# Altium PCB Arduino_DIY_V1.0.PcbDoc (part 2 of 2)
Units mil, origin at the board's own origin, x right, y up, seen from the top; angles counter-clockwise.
Board outline 4006.09 x 4935.69 mil, 2 copper layers (Top Layer, Bottom Layer), stack 46.063 mil thick; 121 components, 93 nets, 429 pads, 83 vias.
Unrouted connection lines stored in the file: 78.
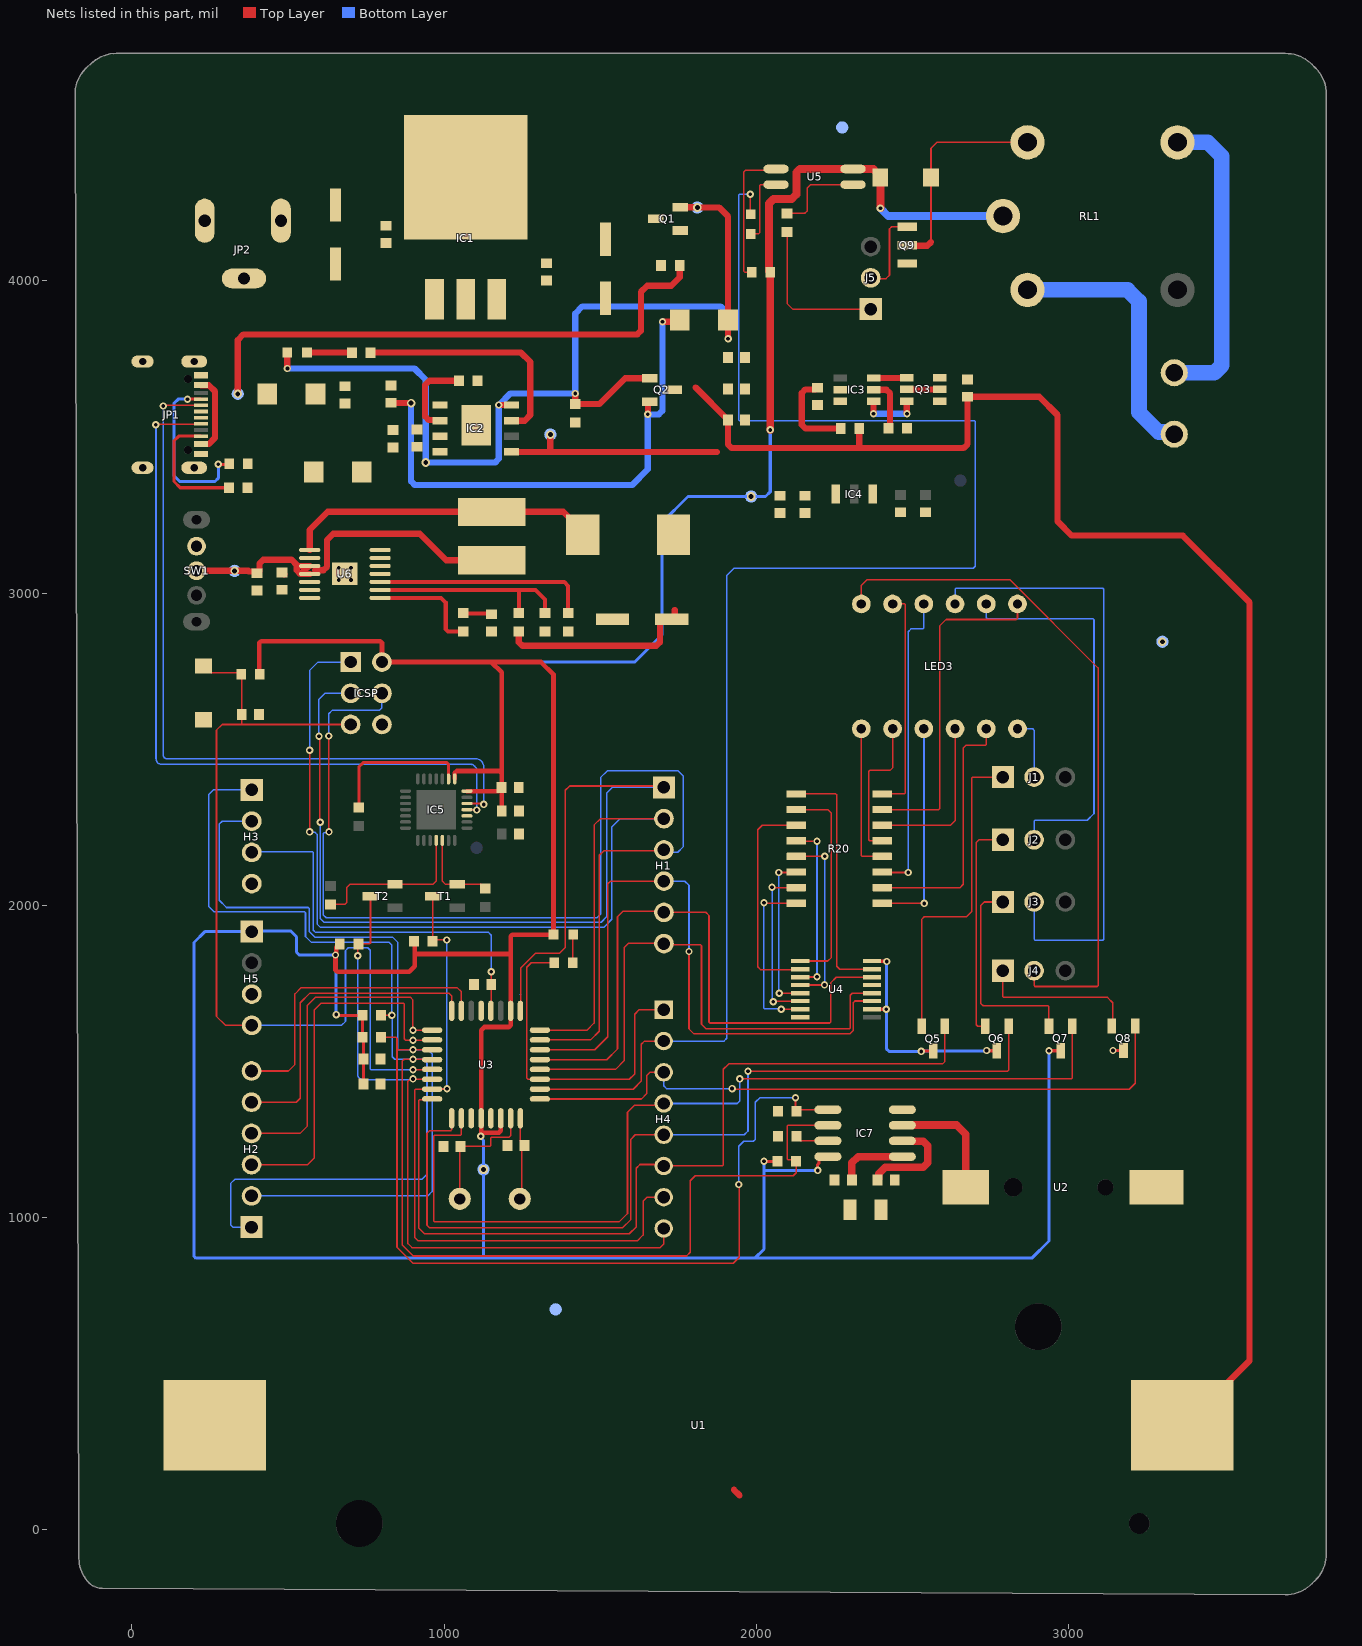
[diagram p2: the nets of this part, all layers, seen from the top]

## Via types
v1: diameter 23.62, hole 11.81, Top Layer to Bottom Layer, 65 vias
v2: diameter 27.56, hole 15.75, Top Layer to Bottom Layer, 11 vias
v3: diameter 24, hole 12, Top Layer to Bottom Layer, 4 vias
v4: diameter 157.48, hole 157.48, Top Layer to Bottom Layer, 3 vias

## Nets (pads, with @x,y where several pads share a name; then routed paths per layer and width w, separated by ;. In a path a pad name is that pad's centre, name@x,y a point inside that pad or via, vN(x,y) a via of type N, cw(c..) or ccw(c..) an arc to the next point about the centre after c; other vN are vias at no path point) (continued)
+5V: C15.1 C16.2 C17.2 C23.2 C24.2 C27.2 C28.2 D4.1 D5.1 H5.1 IC4.3 IC5.7 IC5.8 IC7.8 ICSP.6 LED2.1 Q5.3 Q6.3 Q7.3 Q8.3 R9.2 R11.2 R12.2 R15.2 R17.2 R18.2 R19.2 R21.2 R23.2 R24.2 RL1.5 TP6.1 TP8.1 U3.4 U3.6 U3.18 U4.10 U4.16 U5.4 | length 15890.7
  Top Layer w10: v1(654,1650) 656.61,1647.39 674.61,1647.39 675,1647 675.35,1647.35 R23.2@739,1647.35 R24.2@739,1577.35 ; C28.2@741.44,1427.35 C27.2@741.44,1507.35 R24.2@741.44,1574.91 ; v1(2024,1180) 2067.65,1180 R19.2@2068,1180.35 ; v1(2196,1151) 2195.46,1151.54 2195.46,1169.46 2200.06,1174.06 2200.06,1187.24 2208.17,1195.35 IC7.8@2229,1195.35 ; U4.10@2370.16,1667.56 2370.44,1667.28 2415.72,1667.28 v1(2416,1667) ; U4.16@2370.16,1821.56 2370.94,1820.78 2416.22,1820.78 v1(2417,1820) ; v1(2528,1532) 2530,1534 2538,1534 2538.44,1533.56 Q5.3@2566.16,1533.56 ; v1(2737,1535) 2737.81,1534.19 Q6.3@2770.16,1534.19 ; v1(2937,1534) 2944,1534 2944.19,1534.19 Q7.3@2974.16,1534.19 ; v1(3142,1535) 3142.18,1534.82 Q8.3@3175.56,1534.82
  Top Layer w15: R15.2@409.5,2740.35 408,2752.36 408,2840.14 413.86,2846 794.86,2846 800.72,2840.14 ICSP.6@800.72,2779 1151,2779 ; R12.2@665.69,1876 654.81,1865.12 654.81,1847.5 652,1844.69 v1(652,1841) 652,1792.86 657.86,1787 888,1787 906,1805 906,1844.26 ; R11.2@903.69,1885 906,1882.69 906,1844.26 ; IC5.8@1033.68,2404.73 1033.88,2404.93 1033.88,2423.83 1040.05,2430 1176,2430 1183.89,2422.11 ; IC5.7@1073,2365.4 1173.14,2365.4 1183.89,2376.15 C24.2@1183.89,2377.35 1183.89,2422.11 ; v1(1117,1260) 1118.25,1261.25 1118.25,1599.25 1129,1610 1206.88,1610 1212.74,1615.86 U3.18@1212.74,1662 1212.74,1848.03 ; 1124.11,1272 1175.39,1272 1181.24,1277.86 U3.6@1181.24,1318 ; C23.2@1184.44,2302.35 C24.2@1184.44,2376.8 ; 906,1844.26 1208.97,1844.26 1212.74,1848.03 ; 1151,2779 1310,2779 1350.22,2738.78 LED2.1@1350.22,1906.04 1218.6,1906.04 1212.74,1900.18 1212.74,1848.03 ; 1151,2779 1183.89,2746.11 1183.89,2422.11
  Top Layer w20: R9.2@1239.01,2877.04 1239.01,2842.72 1250.72,2831 1679.28,2831 1691,2842.72 1691,2908.09 1698.91,2916 C15.1@1728.48,2916 ; C15.1@1738.7,2916 1738.7,2945.3
  Top Layer w25: v1(2044.31,3522.31) R21.2@2044.31,4027 2040,4031.31 2040,4247.36 2054.64,4262 2113.36,4262 2128,4276.64 2128,4347 2139,4358 U5.4@2309.15,4358 2309.64,4357.51 2374.44,4357.51 2397,4334.95 D5.1@2397,4331 v1(2397,4232)
  Bottom Layer w10: v1(654,1650) 654,1839 v1(652,1841) 536,1841 527,1850 527,1899 508,1918 386.27,1918 H5.1@383.79,1915.52 233.52,1915.52 199,1881 199,875.86 204.86,870 1131,870 ; ICSP.6@800.72,2779 1610.59,2779 1697,2865.41 1697,3225 1781,3309 v2(1983,3309) 2029,3309 2044.31,3324.31 v1(2044.31,3522.31) ; v1(1117,1260) 1117,1256.31 1126,1247.31 1126,875 1131,870 ; v1(2024,1180) 2024,1151 ; v1(2196,1151) 2024,1151 ; v1(2417,1820) 2416.5,1819.5 2416.5,1667.5 v1(2416,1667) 2416,1541 2425,1532 v1(2528,1532) 2529.5,1533.5 2735.5,1533.5 v1(2737,1535) ; v1(2937,1534) 2937,925 2882,870 1995,870 ; 1131,870 1995,870 ; 1995,870 2024,899 2024,1151
  Bottom Layer w25: v1(2397,4232) 2422,4207 RL1.5@2789.47,4207
  other v2: 1126,1154
+5V_B: D1.2 D3.2 JP1.A9B4 JP1.B9A4 Q1.1 R3.2 TP1.1 | length 2034.9
  Top Layer w20: JP1.A9B4@221.83,3476.86 221.98,3477.02 245.95,3477.02 266,3497.07 266,3645.67 245.99,3665.68 221.98,3665.68 JP1.B9A4@221.83,3665.84 ; v2(339,3638) 339,3810 357,3828 1618.28,3828 1630,3839.72 1630,3964 1650,3984 1727,3984 1754.31,4011.31 R3.2@1754.31,4049
ADC0: H2.6 U3.23 | length 981.8
  Top Layer w5: H2.6@383,1469.35 501.35,1469.35 522,1490 522,1716 542.54,1736.54 1041.46,1736.54 1055.26,1722.74 U3.23@1055.26,1662
ADC1: H2.5 U3.24 | length 1016.7
  Top Layer w5: H2.5@383,1369.35 526.35,1369.35 539,1382 539,1688 570,1719 1015,1719 1023.76,1710.24 U3.24@1023.76,1662
ADC2: H2.4 U3.25 | length 1086.1
  Top Layer w5: H2.4@383,1269.35 538.35,1269.35 561,1292 561,1678 589,1706 891,1706 900,1697 v1(900,1600) ; v1@900.12,1600.12 961.38,1600.12 U3.25@961.5,1600.24
ADC3: H2.3 U3.26 | length 1181.6
  Top Layer w5: H2.3@383,1169.35 562.35,1169.35 584,1191 584,1665 606,1687 869.07,1687 872,1684.07 872,1572.37 876.37,1568 v1(900,1568) ; v1@904,1568 904.37,1568.37 961.13,1568.37 U3.26@961.5,1568.74
AREF: C29.2 H3.3 U3.20 | length 1267.8
  Top Layer w5: U3.20@1149.75,1662 1150.15,1662.4 1150.15,1745.6 1151,1746.44 v1(1151,1787)
  Bottom Layer w5: H3.3@383.79,2169.35 386.51,2172.07 578,2172.07 580.93,2169.14 580.93,1920.07 588,1913 1142,1913 1151,1904 v1(1151,1787)
DATA+: IC5.4 JP1.A6 JP1.B6 | length 2424
  Top Layer w5: v1(76,3539) 77.41,3540.41 220.41,3540.41 JP1.B6@221.82,3541.82 ; IC5.4@1073,2306.3 1073.59,2305.71 1104.06,2305.71 v1(1104.65,2305.12)
  Bottom Layer w5: v1(76,3539) 77.07,3537.93 77.07,2468.93 ccw(c94,2468.93) 94,2452 1082,2452 cw(c1082,2429.35) 1104.65,2429.35 v1(1104.65,2305.12)
DATA-: IC5.5 JP1.A7 JP1.B7 | length 2464.1
  Top Layer w5: v1(100,3599) 101.88,3600.88 JP1.B7@221.83,3600.88 ; IC5.5@1073,2326 1124,2326 v1(1127,2323)
  Bottom Layer w5: v1(100,3599) 100,2482 ccw(c113,2482) 113,2469 1101,2469 cw(c1101,2443) 1127,2443 v1(1127,2323)
DIG1: H4.6 Q5.1 U3.32 | length 2781.6
  Top Layer w5: U3.32@961.5,1379.76 959.07,1377.33 920.93,1377.33 918,1374.4 918,967 937,948 1593,948 1615,970 1615,1158 1627,1170 1698.24,1170 H4.6@1703,1165.24 1891.07,1165.24 1894,1168.17 1894,1475 1911,1492 2596,1492 2603.56,1499.56 Q5.1@2603.56,1612.3
DIG2: H4.5 Q6.1 U3.1 | length 2894.4
  Top Layer w5: U3.1@1023.76,1318 1023.76,1280.93 1020.83,1278 953,1278 945,1270 945,975 953,967 1571,967 1598,994 1598,1251 1612.24,1265.24 H4.5@1703,1265.24 ; v1(1973,1469) 2804.63,1469 2807.56,1471.93 Q6.1@2807.56,1612.93
  Bottom Layer w5: H4.5@1703,1265.24 1961.24,1265.24 1973,1277 v1(1973,1469)
DIG3: H4.4 Q7.1 U3.2 | length 3049.4
  Top Layer w5: U3.2@1055.26,1318 1055.26,1266.93 1052.33,1264 968.93,1264 966,1261.07 966,988.93 968.93,986 1560,986 1587,1013 1587,1337 1609,1359 1696.76,1359 H4.4@1703,1365.24 ; v1(1947,1444) 3008.63,1444 3011.56,1446.93 Q7.1@3011.56,1612.93
  Bottom Layer w5: H4.4@1703,1365.24 1938.24,1365.24 1947,1374 v1(1947,1444)
DIG4: H4.3 Q8.1 U3.9 | length 2215.1
  Top Layer w5: U3.9@1306.5,1379.76 1631.76,1379.76 1649,1397 1649,1455 1659.24,1465.24 H4.3@1703,1465.24 ; v1(1922,1413) 1924,1411 3194,1411 3212.96,1429.96 Q8.1@3212.96,1613.56
  Bottom Layer w5: H4.3@1703,1465.24 1703,1421.93 1711.93,1413 v1(1922,1413)
DS: H1.5 U3.13 U4.14 | length 1990.3
  Top Layer w5: U3.13@1306.5,1505.75 1520.75,1505.75 1555,1540 1555,1963 1573,1981 1700.14,1981 H1.5@1703.79,1977.35 1837.65,1977.35 1848,1967 1848,1625.93 1850.93,1623 2234,1623 2237.31,1626.31 2237.31,1751.31 2255.56,1769.56 U4.14@2370.16,1769.56
GND: C1.1 C2.1 C3.2 C4.2 C5.1 C6.1 C7.1 C9.1 C10.1 C11.1 C13.1 C14.1 C15.2 C16.1 C17.1 C18.1 C19.1 C20.1 C21.1 C22.1 C23.1 C24.1 C25.2 C26.2 C27.1 C28.1 C29.1 C30.2 C31.2 C32.2 H3.4 H5.3 IC1.2 IC1.4 IC2.1 IC2.3 IC2.9 IC4.1 IC5.3 IC7.4 ICSP.4 JP1.17 JP1.18 JP1.19 JP1.20 JP1.A12B1 JP1.B12A1 JP2.2 JP2.3 Q3.1 Q9.3 R1.1 R2.1 R3.1 R6.1 R7.1 R8.1 R26.1 R27.1 RESET.2 TP9.1 TP10.1 TP11.1 U2.2 U3.3 U3.5 U3.21 U4.8 U4.13 U6.6 U6.7 U6.11 U6.12 U6.13 U6.14 U6.15
  other v2: 3300,2844
  other v3: 662.31,3041.31 701.68,3041.31 662.31,3080.68 701.68,3080.68
MISO: H1.2 ICSP.1 U3.16 | length 3457
  Top Layer w5: v1@569,2234 v1(569,2496) ; U3.16@1306.5,1600.24 1457.24,1600.24 1480,1623 1480,2257 1500.35,2277.35 H1.2@1703.79,2277.35
  Bottom Layer w5: v1@569,2234 586,2234 592.99,2227.01 592.99,1940.01 604,1929 1511,1929 1537,1955 1537,2251 1563.35,2277.35 H1.2@1703.79,2277.35 ; v1(569,2496) 569,2752 596,2779 ICSP.1@700.72,2779
  other v1: 569,2235
MOSI: H1.3 ICSP.5 U3.15 | length 3778.9
  Top Layer w5: v1(630,2542) 630.5,2541.5 630.5,2235.5 v1(631,2235) ; U3.15@1306.5,1568.74 1468.74,1568.74 1497,1597 1497,2160 1512,2175 1701.44,2175 H1.3@1703.79,2177.35
  Bottom Layer w5: v1(630,2542) 630,2613 641,2624 792,2624 800,2632 800,2678.28 ICSP.5@800.72,2679 ; v1(631,2235) 628.77,2232.77 615.92,2232.77 612.99,2229.84 612.99,1969.01 622,1960 1489,1960 1501.93,1972.93 1501.93,1977.07 1501,1978 1501,2409 1523,2431 1749,2431 1765,2415 1765,2187 1747.86,2169.85 1714.99,2169.85 1713.14,2168 H1.3@1703.79,2177.35
NetC3_1: C3.1 C6.2 IC1.1 JP2.1
NetC4_1: C4.1 C5.2 IC1.3 Q1.3
NetC8_1: C8.1 C12.1 IC3.6 Q3.3 U1.2 | length 44.9
  Top Layer w20: U1.2@265.99,335 U1.2@285.48,335 ; 1928,128 1946,110
NetC8_2: C8.2 IC3.5 R5.1 | length 290.7
  Top Layer w20: C8.2@2195,3657.56 2189.39,3651.95 2156.72,3651.95 2145,3640.23 2145,3538.72 2156.72,3527 R5.1@2270,3527 ; IC3.5@2267.75,3652.81 IC3.5@2268.85,3651
NetC9_2: C9.2 C10.2 C11.2 C12.2 IC2.5 Q2.3 R5.2 TP3.1 U1.1 | length 6033.5
  Top Layer w20: IC2.5@1215.5,3452 1340,3452 ; v2(1340,3507.35) 1340,3452 ; 1805,3658.06 C11.2@1908.67,3554.39 ; 1873,3452 1340,3452 ; C11.2@1908.67,3553.96 1908.67,3475.72 1920.38,3464 2329.31,3464 ; R5.2@2329.31,3527 2329.31,3464 ; U1.1@3364.01,335 3372.32,335 3579,541.68 3579,2970 3365.05,3183.95 3010.05,3183.95 2964,3230 2964,3570 2905.55,3628.45 C12.2@2676,3628.45 2676,3477 2663,3464 2329.31,3464
NetC14_2: C14.2 L1.1 SW1.2 TP4.1 U6.3 U6.4 | length 1189.7
  Top Layer w20: SW1.2@207,3071.35 207.18,3071.18 328.82,3071.18 v2(329,3071) 372.78,3071 374.48,3069.3 395.25,3069.3 C14.2@401,3063.56 402.97,3063.56 408.72,3069.3 408.72,3094.65 420.43,3106.36 511.32,3106.36 527.9,3089.78 527.9,3072.72 539.61,3061 549.9,3061 U6.4@569.17,3061 ; 527.9,3086.59 U6.3@569.17,3086.59 ; 549.9,3070.9 U6.3@565.59,3086.59 ; 586.16,3073 613.28,3073 625,3084.72 625,3170 645,3190 922,3190 1007,3105 L1.1@1152,3105
NetC20_2: C20.2 U6.5 | length 10.1
  Top Layer w20: C20.2@481,3065.56 486.75,3059.81 C20.2@488.72,3059.81
NetC21_2: C21.2 R25.1 | length 91.8
  Top Layer w13: R25.1@1061,2936.35 1063.14,2934.2 1148.85,2934.2 C21.2@1151,2932.06
NetC31_1: C31.1 IC7.2 X2.2 | length 335.1
  Top Layer w24: C31.1@2388,1120.35 2391.75,1124.1 2391.75,1140.75 2412,1161 2533.94,1161 2548,1175.06 2548,1230.61 2533.94,1244.67 2467.68,1244.67 IC7.2@2467,1245.35
NetC32_1: C32.1 IC7.1 X2.1 | length 224.8
  Top Layer w24: C32.1@2305.55,1120.35 2305.5,1120.41 2305.5,1175.35 2325.5,1195.35 IC7.1@2467,1195.35
NetD4_2: D4.2 L1.2 U6.1 U6.2 | length 1000.6
  Top Layer w20: U6.1@569.17,3137.77 569.17,3202.18 627,3260 L1.2@1152,3260 1381.68,3260 1443.87,3197.81 D4.2@1443.87,3186
NetD5_2: D5.2 Q9.2 RL1.4 | length 699.2
  Top Layer w5: 2559,4123.72 D5.2@2559,4331 2559,4424 2578.22,4443.22 RL1.4@2868.21,4443.22
  Top Layer w20: Q9.2@2483,4114.06 2485.05,4112 2547.28,4112 2559,4123.72
NetH2_1: H2.1 H3.1 IC7.6 R19.1 R23.1 U3.28 | length 5405.3
  Top Layer w5: R23.1@798.31,1647.35 798.96,1648 v1(832.69,1648) ; v1(900,1507) 872,1507 866,1501 866,912 901,877 1776,877 1788,889 1788,1118 1804,1134 2118,1134 2127.31,1143.31 R19.1@2127.31,1180.35 2122.66,1185 2100.93,1185 2098,1187.93 2098,1292.42 2100.93,1295.35 IC7.6@2229,1295.35 ; v1@905,1507 905.63,1506.37 960.87,1506.37 U3.28@961.5,1505.75
  Bottom Layer w5: H2.1@383,969.35 323.65,969.35 316,977 316,1109 329,1122 928,1122 945,1139 945,1494.62 932.62,1507 v1(900,1507) 842,1507 834,1515 834,1646.69 v1(832.69,1648) 832.69,1872.31 824,1881 575,1881 556,1900 556,1976.07 553.07,1979 263,1979 246,1996 246,2355 260.35,2369.35 H3.1@383.79,2369.35
NetH2_2: H2.2 H3.2 IC7.5 R18.1 R24.1 U3.27 | length 5276.8
  Top Layer w5: R24.1@798.31,1577.35 846.07,1577.35 849,1574.42 849,1537.24 ; U3.27@961.5,1537.24 849,1537.24 ; v1(1943,1106) 1945,1104 1945,873 1926,854 900,854 849,905 849,1537.24 ; v1(2125,1384) 2125,1343.35 R18.1@2128,1340.35 2133,1345.35 IC7.5@2229,1345.35
  Bottom Layer w5: H2.2@383,1069.35 947.35,1069.35 961.19,1083.19 961.19,1524.81 948.76,1537.24 v1@907,1537.24 ; H3.2@383.79,2269.35 289.35,2269.35 280,2260 280,2016 303,1993 565.07,1993 568,1990.07 568,1916 587,1897 836,1897 852,1881 852,1540.17 854.93,1537.24 v1(900,1537.24) ; v1(1943,1106) 1943,1228 1959,1244 1990,1244 1996,1250 1996,1369 2011,1384 v1(2125,1384)
NetH6_1: H6.1 RL1.1 | length 869.5
  Bottom Layer w50: RL1.1@2868.21,3970.78 3188.22,3970.78 3225,3934 3225,3578.43 3287.85,3515.58 3330.99,3515.58 H6.1@3338,3508.57
NetH6_2: H6.2 RL1.3 | length 992.1
  Bottom Layer w50: H6.2@3338,3705.43 3466.44,3705.43 3490.66,3729.64 3490.66,4398.34 3445.8,4443.2 RL1.3@3348.53,4443.2
NetIC2_2: IC2.2 R6.2 | length 268.3
  Top Layer w20: IC2.2@986.5,3552 984.69,3553.81 950.72,3553.81 939,3565.53 939,3666.36 952.64,3680 R6.2@1047.69,3680
NetIC2_7: IC2.7 R4.2 | length 762.1
  Top Layer w20: R4.2@764.31,3770 1246,3770 1276,3740 1276,3570 1258,3552 IC2.7@1215.5,3552
NetIC3_1: IC3.1 Q3.6 | length 187.7
  Top Layer w20: v1(2375,3574) 2375.15,3574.15 IC3.1@2375.15,3613.6 ; Q3.6@2481,3614.6 2481.5,3614.1 2481.5,3574.5 v1(2482,3574)
  Bottom Layer w20: v1(2375,3574) v1(2482,3574)
NetIC3_2: IC3.2 R7.2 | length 171.2
  Top Layer w20: IC3.2@2375.15,3651 2416.28,3651 2428,3639.28 2428,3533.31 R7.2@2422.69,3528
NetIC3_3: IC3.3 Q3.4 | length 106.3
  Top Layer w20: IC3.3@2375.15,3688.4 2375.65,3688.9 2480.5,3688.9 Q3.4@2481,3689.4
NetIC5_9: IC5.9 R14.1 | length 471
  Top Layer w10: R14.1@727,2313.66 727,2443 741,2457 1008.12,2457 1013.98,2451.14 IC5.9@1013.98,2404.73
NetIC7_3: IC7.3 U2.1 | length 385.5
  Top Layer w25: IC7.3@2467,1295.35 2467.65,1296 2641,1296 2670.43,1266.57 U2.1@2670.43,1097
NetIC7_7: IC7.7 R17.1 | length 107.8
  Top Layer w5: R17.1@2128,1260.35 2128,1259.38 2141.38,1246 2228.35,1246 IC7.7@2229,1245.35
NetJ1_1: J1.1 Q5.2 | length 1042.7
  Top Layer w5: Q5.2@2528.76,1612.3 2528.76,1954.76 2537,1963 2673,1963 2689,1979 2689,2407.64 2691.93,2410.56 J1.1@2789.16,2410.56
NetJ1_2: J1.2 LED3.6 | length 205.8
  Bottom Layer w5: LED3.6@2836,2565 2885,2565 2889.93,2560.07 2889.93,2499.1 2889.16,2498.33 J1.2@2889.16,2410.56
NetJ2_1: J2.1 Q6.2 | length 703.1
  Top Layer w5: Q6.2@2732.76,1612.93 2708.38,1612.93 2704,1617.31 2704,2201 2712.78,2209.78 J2.1@2789.16,2209.78
NetJ2_2: J2.2 LED3.8 | length 1274.3
  Bottom Layer w5: LED3.8@2736,2965 2736,2920.93 2738.93,2918 3078.07,2918 3081,2915.07 3081,2294 3059,2272 2891.93,2272 2889,2269.07 2889,2209.94 J2.2@2889.16,2209.78
NetJ3_1: J3.1 Q7.2 | length 673.5
  Top Layer w5: J3.1@2789.16,2010.56 2729.56,2010.56 2719,2000 2719,1685 2726,1678 2933.83,1678 2936.76,1675.07 Q7.2@2936.76,1612.93
NetJ3_2: J3.2 LED3.9 | length 1991
  Bottom Layer w5: LED3.9@2636,2965 2636,3012.07 2638.93,3015 3109.07,3015 3112,3012.07 3112,1890.93 3109.07,1888 2893,1888 2889.16,1891.84 J3.2@2889.16,2010.56
NetJ4_1: J4.1 Q8.2 | length 518.4
  Top Layer w5: J4.1@2789.16,1790.56 2789.16,1707.77 2792.09,1704.84 3124.16,1704.84 3141,1688 3141,1616.4 Q8.2@3138.16,1613.56
NetJ4_2: J4.2 LED3.12 | length 2214.1
  Top Layer w5: LED3.12@2336,2965 2336,3024 2354.93,3042.93 2811.11,3042.93 3094,2760.03 3094,1742.91 3091.07,1739.98 2892.09,1739.98 2889.16,1742.91 J4.2@2889.16,1790.56
NetJ5_1: J5.1 R22.2 | length 505
  Top Layer w5: R22.2@2098,4156.69 2098,3927 2115.65,3909.35 J5.1@2366,3909.35
NetJ5_2: J5.2 Q9.1 | length 273.7
  Top Layer w5: J5.2@2366,4009.35 2368.42,4006.93 2415.21,4006.93 2426,4017.72 2426,4166 2433.11,4173.11 Q9.1@2483,4173.11
NetJP1_A5: JP1.A5 R1.2 | length 559.1
  Top Layer w10: v1(178,3621) 178.22,3620.78 221.61,3620.78 JP1.A5@221.82,3620.56 ; v1(277,3412) 309.34,3412 R1.2@311.69,3414.35
  Bottom Layer w10: v1(178,3621) 148,3621 135,3608 135,3375 153,3357 266,3357 277,3368 v1(277,3412)
NetJP1_B5: JP1.B5 R2.2 | length 408.1
  Top Layer w10: JP1.B5@221.82,3502.45 149.45,3502.45 135,3488 135,3357 155,3337 R2.2@311,3337
NetLED1_2: LED1.2 R4.1 | length 144.7
  Top Layer w10: R4.1@704.65,3770.35 R4.1@705,3770
  Top Layer w20: LED1.2@560.47,3770.35 R4.1@704.65,3770.35
NetLED2_2: LED2.2 R16.2 | length 90.6
  Top Layer w5: R16.2@1411.69,1816.04 1411.69,1904.57 LED2.2@1413.17,1906.05
NetLED3_1: LED3.1 R20.12 | length 473.5
  Top Layer w5: LED3.1@2336,2565 2336,2159.49 2338.93,2156.56 R20.12@2402.76,2156.56
NetLED3_2: LED3.2 R20.13 | length 469.1
  Top Layer w5: R20.13@2402.76,2206.56 2362.93,2206.56 2360,2209.49 2360,2429.07 2362.93,2432 2428,2432 2436,2440 LED3.2@2436,2565
NetLED3_3: LED3.3 R20.9 | length 693.9
  Top Layer w5: R20.9@2402.76,2006.56 2403.32,2006 v1(2537,2006)
  Bottom Layer w5: LED3.3@2536,2565 2536.5,2564.5 2536.5,2006.5 v1(2537,2006)
NetLED3_4: LED3.4 R20.14 | length 533.2
  Top Layer w5: R20.14@2402.76,2256.56 2621.56,2256.56 2636,2271 LED3.4@2636,2565
NetLED3_5: LED3.5 R20.10 | length 829.2
  Top Layer w5: R20.10@2402.76,2056.56 2651.56,2056.56 2662,2067 2662,2504 2670,2512 2733.07,2512 2736,2514.93 LED3.5@2736,2565
NetLED3_7: LED3.7 R20.15 | length 1075.6
  Top Layer w5: R20.15@2402.76,2306.56 2583.63,2306.56 2586.56,2309.49 2586.56,2894.56 2607.23,2915.23 2832.13,2915.23 2836,2919.1 LED3.7@2836,2965
NetLED3_10: LED3.10 R20.11 | length 986.9
  Top Layer w5: R20.11@2402.76,2106.56 2404.32,2105 v1(2486,2105)
  Bottom Layer w5: v1(2486,2105) 2486,2876 2495,2885 2533.07,2885 2536,2887.93 LED3.10@2536,2965
NetLED3_11: LED3.11 R20.16 | length 720.2
  Top Layer w5: R20.16@2402.76,2356.56 2474.07,2356.56 2477,2359.49 2477,2962.07 2474.07,2965 LED3.11@2436,2965
NetLED4_1: LED4.1 U5.2 | length 234.4
  Top Layer w5: LED4.1@1982,4149.88 1982.6,4150.47 2006.71,4150.47 2011,4154.77 2011,4305.07 2013.93,4308 U5.2@2062.85,4308
NetQ3_2: Q3.2 Q3.5 | length 106.3
  Top Layer w20: Q3.5@2481,3652 Q3.2@2587.31,3652
NetR9_1: R9.1 R26.2 U6.9 | length 657.5
  Top Layer w13: U6.9@794.83,3009.82 1238,3009.82 ; R9.1@1239.01,2936.35 1239.01,3008.81 1238,3009.82 ; R26.2@1323.01,2936.35 1323.01,2978.99 1292.18,3009.82 1238,3009.82
NetR20_1: R20.1 U4.15 | length 796.3
  Top Layer w5: R20.1@2127.56,2356.56 2254.07,2356.56 2257,2353.63 2257,1805.04 2266.47,1795.56 U4.15@2370.16,1795.56
NetR20_2: R20.2 U4.1 | length 683.8
  Top Layer w5: R20.2@2127.56,2306.56 2228.44,2306.56 2240,2295 2240,1833 2228.56,1821.56 U4.1@2140.16,1821.56
NetR20_3: R20.3 U4.2 | length 709.1
  Top Layer w5: R20.3@2127.56,2256.56 2018.56,2256.56 2004,2242 2004,1803 2013,1794 2138.6,1794 U4.2@2140.16,1795.56
NetR20_4: R20.4 U4.3 | length 543.7
  Top Layer w5: R20.4@2127.56,2206.56 2129.13,2205 2180,2205 ; U4.3@2140.16,1769.56 2140.88,1770.28 2193.28,1770.28 v1(2194,1771)
  Bottom Layer w5: v1(2194,1771) v1@2194,2207.13
  other v1: 2194,2205
NetR20_5: R20.5 U4.4 | length 582.4
  Top Layer w5: R20.5@2127.56,2156.56 2218.56,2156.56 v1(2219,2157) ; U4.4@2140.16,1744.56 2140.38,1744.78 2217.78,1744.78 v1(2218,1745)
  Bottom Layer w5: v1(2218,1745) 2217.57,1745.43 2217.57,1749.57 2219,1751 v1(2219,2157)
NetR20_6: R20.6 U4.5 | length 512.4
  Top Layer w5: v1(2071,2105) 2126,2105 R20.6@2127.56,2106.56 ; v1(2073,1718) 2073.28,1718.28 2139.88,1718.28 U4.5@2140.16,1718.56
  Bottom Layer w5: v1(2071,2105) 2071,1720 v1(2073,1718)
NetR20_7: R20.7 U4.6 | length 534
  Top Layer w5: v1(2050,2058) 2051,2057 2054,2057 2054.44,2056.56 R20.7@2127.56,2056.56 ; v1(2054,1691) 2055.28,1692.28 2138.88,1692.28 U4.6@2140.16,1693.56
  Bottom Layer w5: v1(2050,2058) 2050,1698 2054,1694 v1(2054,1691)
NetR20_8: R20.8 U4.7 | length 559.2
  Top Layer w5: v1(2024,2008) 2025,2007 2035,2007 2035.44,2006.56 R20.8@2127.56,2006.56 ; v1(2079,1667) 2079.28,1667.28 2139.88,1667.28 U4.7@2140.16,1667.56
  Bottom Layer w5: v1(2024,2008) 2024,1670.93 2026.93,1668 2077,1668 2078,1667 v1(2079,1667)
NetR21_1: R21.1 U5.1 | length 452.8
  Top Layer w5: R21.1@1985,4027 1963.05,4027 1958.75,4031.3 1958.75,4347.75 1965,4354 2058.85,4354 U5.1@2062.85,4358
NetR22_1: R22.1 U5.3 | length 292
  Top Layer w5: R22.1@2098,4216 2155,4216 2162,4223 2162,4296 2174,4308 U5.3@2309.15,4308
NetR25_2: R25.2 U6.8 | length 360
  Top Layer w13: U6.8@794.83,2984.23 989.77,2984.23 1005,2969 1005,2884.65 1012.62,2877.04 R25.2@1061,2877.04
NetR27_2: R27.2 U6.10 | length 694
  Top Layer w13: U6.10@794.83,3035.41 1384.59,3035.41 1397,3023 R27.2@1397,2936.35
PD7: H4.1 R16.1 U3.11 | length 1093.2
  Top Layer w5: R16.1@1352.38,1816.04 1279.04,1816.04 1264.31,1801.31 1264.31,1446.69 1268.24,1442.76 U3.11@1306.5,1442.76 1592.76,1442.76 1610,1460 1610,1651 1624.24,1665.24 H4.1@1703,1665.24
RELAY: H4.2 LED4.2 U3.10 | length 5071.3
  Top Layer w5: U3.10@1306.5,1411.26 1605.26,1411.26 1631,1437 1631,1555 1641.24,1565.24 H4.2@1703,1565.24 ; v1(1980,4277) 1980,4214.82 LED4.2@1982,4212.83
  Bottom Layer w5: H4.2@1703,1565.24 1896.24,1565.24 1905,1574 1905,3056 1928,3079 2694,3079 2701,3086 2701,3549.07 2698.07,3552 1945.93,3552 1943,3554.93 1943,4274.07 1945.93,4277 v1(1980,4277)
RESET: C30.1 H5.4 ICSP.3 R15.1 RESET.1 U3.29 | length 2968.4
  Top Layer w5: RESET.1@229.5,2766.38 253.77,2745 336.81,2745 R15.1@350.19,2740.35 351.74,2725.84 351.74,2625.57 C30.1@351.94,2610.35 351.41,2609.82 351.41,2579 ; H5.4@383.79,1615.52 299.48,1615.52 271,1644 271,2561 289,2579 351.41,2579 ; ICSP.3@700.72,2579 351.41,2579 ; v1@900,1473.63 960.87,1473.63 U3.29@961.5,1474.25
  Bottom Layer w5: H5.4@383.79,1615.52 671.52,1615.52 684,1628 684,1855 693,1864 755,1864 763,1856 763,1475.93 765.93,1473 v1(900,1473)
RX: H4.7 R11.1 T1.3 U3.31 | length 2167
  Top Layer w5: R11.1@963,1885 R11.1@963.63,1885.63 ; T1.3@963.63,2029.35 R11.1@963.63,1885.63 ; v1(1008,1889) 967,1889 R11.1@963.63,1885.63 ; v1(1009,1412) 1008.63,1411.63 961.87,1411.63 U3.31@961.5,1411.26 908.93,1411.26 906,1408.33 906,936 916,926 1619,926 1637,944 1637,1052.48 1649.76,1065.24 H4.7@1703,1065.24
  Bottom Layer w5: v1(1008,1889) 1008.5,1888.5 1008.5,1412.5 v1(1009,1412)
RX_TO_MCU: IC5.25 R10.1 T2.2 | length 528
  Top Layer w5: R10.1@636,2002.69 681.69,2002.69 688,2009 688,2057 697.75,2066.75 T2.2@842.37,2066.75 963.75,2066.75 974.58,2077.58 IC5.25@974.58,2207.88
SCK: H1.1 ICSP.2 U3.17 | length 3466.7
  Top Layer w5: v1(599,2541) 601,2539 601,2268 v1(603,2266) ; U3.17@1244.24,1662 1244.62,1662.38 1244.62,1798.62 1293,1847 1370,1847 1388,1865 1388,2368 1402,2382 1699.14,2382 H1.1@1703.79,2377.35
  Bottom Layer w5: v1(599,2541) 599,2660 618,2679 ICSP.2@700.72,2679 ; v1(603,2266) 603,2234 602.99,1958.01 615,1946 1503,1946 1520,1963 1520,2359 1538.35,2377.35 H1.1@1703.79,2377.35 ; 1243,1715 1245,1713
SH_CP: H1.4 U3.14 U4.11 | length 2142.4
  Top Layer w5: U3.14@1306.5,1537.24 1482.24,1537.24 1524,1579 1524,2069 1532.35,2077.35 H1.4@1703.79,2077.35 ; v1(1784,1852) 1784,1604 1800,1588 2299,1588 2310,1599 2310,1688 2315.56,1693.56 U4.11@2370.16,1693.56
  Bottom Layer w5: H1.4@1703.79,2077.35 1770.65,2077.35 1784,2064 v1(1784,1852)
ST_CP: H1.6 U3.12 U4.12 | length 1813.4
  Top Layer w5: U3.12@1306.5,1474.25 1548.25,1474.25 1577,1503 1577,1865 1591,1879 1702.14,1879 H1.6@1703.79,1877.35 1708.14,1873 1821.07,1873 1824,1870.07 1824,1619 1839,1604 2297.07,1604 2300,1606.93 2300,1712 2306.56,1718.56 U4.12@2370.16,1718.56
TX: H4.8 R12.1 T2.3 U3.30 | length 2256.7
  Top Layer w5: v1(723,1838) 723,1874 R12.1@725,1876 ; 741.31,1876.35 761.14,1876.35 764.07,1879.28 T2.3@764.07,2029.35 ; v1(900,1444) 896.44,1440.44 887.6,1440.44 884,1436.83 884,917 897,904 1691.76,904 1703,915.24 H4.8@1703,965.24 ; v1@907,1444 907.62,1443.38 960.88,1443.38 U3.30@961.5,1442.76
  Bottom Layer w5: v1(723,1838) 723,1458.44 ccw(c739.44,1458.44) 739.44,1442 v1@905,1442
TX_TO_MCU: IC5.26 R13.1 T1.2 | length 277.1
  Top Layer w5: IC5.26@994.28,2207.88 994.28,2076.72 1004.25,2066.75 T1.2@1042.37,2066.75 1118.6,2066.75 R13.1@1131,2054.35
VCC: C7.2 C13.2 D2.2 D3.1 IC2.4 IC2.8 LED1.1 Q1.2 Q2.1 R8.2 TP2.1 | length 3194.4
  Top Layer w20: LED1.1@497.52,3770.35 497.52,3719.48 v1(498,3719) ; v1(1175,3602) IC2.8@1215.5,3602 ; v1(1420,3639) R8.2@1420,3605 1497,3605 1579.8,3687.8 Q2.1@1658,3687.8 ; Q1.2@1755.74,4235.75 1756.35,4235.14 1810.21,4235.14 v2(1810.82,4234.53) 1880.47,4234.53 1909.16,4205.84 D2.2@1909.16,3874.05 v1(1909.16,3814.16)
  Bottom Layer w20: v1(498,3719) 905,3719 941,3683 v2(941,3418) 1163.28,3418 1175,3429.72 v1(1175,3602) 1212,3639 v1(1420,3639) 1420,3895 1442.84,3917.84 1885.17,3917.84 1909.16,3893.84 v1(1909.16,3814.16)
VIN: C1.2 C2.2 D1.1 D2.1 Q2.2 SW1.1 | length 1713.9
  Top Layer w20: C1.2@830,3609.45 830.72,3608.72 893.28,3608.72 v2(894,3608) ; v1(1652,3572) 1652.69,3572.69 1652.69,3609.22 1656.47,3613 Q2.2@1658,3613 ; v1(1699,3869) 1749.78,3869 D2.1@1754.84,3874.05
  Bottom Layer w20: v2(894,3608) 894,3357.72 905.72,3346 1602,3346 1652,3396 v1(1652,3572) 1687.28,3572 1699,3583.72 v1(1699,3869)
XTAL1: C25.1 U3.7 X1.2 | length 412.8
  Top Layer w5: X1.2@1049.94,1060 1049.94,1225.38 C25.1@1052.56,1228 1146.07,1228 1149,1230.93 1149,1254.07 1151.93,1257 1207.48,1257 1212.74,1262.26 U3.7@1212.74,1318
XTAL2: C26.1 U3.8 X1.1 | length 269.9
  Top Layer w5: X1.1@1242.06,1060 1248,1065.94 1248,1219.48 C26.1@1257.56,1229.03 ; U3.8@1244.24,1318 1244.24,1249.15 1244.31,1249.07 1244.31,1244.25 C26.1@1257.56,1231
  Top Layer w20: C26.1@1257.56,1229.03 C26.1@1257.56,1231
pads on no net: IC2.6 IC3.4 IC5.1 IC5.2 IC5.10 IC5.11 IC5.12 IC5.13 IC5.14 IC5.15 IC5.16 IC5.17 IC5.18 IC5.19 IC5.20 IC5.21 IC5.22 IC5.23 IC5.24 IC5.27 IC5.28 IC5.29 J1.3 J2.3 J3.3 J4.3 J5.3 JP1. JP1.A8 JP1.B8 RL1.2 SW1.3 SW1.4 U1. U2. U3.19 U3.22 U4.9
copper on no net:
  other v4: 3,-3.05 3.12,4559.07 3635,4560

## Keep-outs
Keep-Out Layer:
  lines w7.87: -133.61,4692.28 ccw(c-63.14,4595.96) -181.06,4614.33 -169.44,-91.6 ccw(c-57.87,-91.6) -136.76,-170.5 ; -130.96,4694.59 cw(c-49.9,4613.53) -49.9,4728.17 3608.61,4728.17 ; 138.25,4728 145,4728 ; 3608.61,4728 3694,4728 cw(c3694,4607.29) 3779.35,4692.65 3789.65,4682.35 cw(c3704.29,4597) 3825,4597 3825,-75.9 ccw(c3826.56,-75.9) 3825.46,-77 ; 3651.31,4728 3653,4728 ; 3825.03,-76.52 cw(c3704.32,-76.52) 3789.67,-161.88 3779.38,-172.17 cw(c3694.03,-86.81) 3694.03,-207.52 -95.74,-187.49 cw(c-95.74,-129.48) -136.76,-170.5 ; -136.76,-170.5 -136.76,-170.5

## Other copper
Top Layer:
  region net +5V: 1202,1822 1203,1813 1203,1628 1193,1619 1192,1619 1120,1619 1104,1603 1104,1243 1109,1243 1129,1243 1133,1243 1134,1591 1140,1597 1214,1597 1227,1610 1227,1818 1225,1820
  region net NetC8_1: 3152,3364 3728,3364 3787,3305 3787,3053 3694,3053 3692,3051 3687,3056 3687,3211 3634,3264 3152,3264
  region net +5V: 2028,4044 2060,4044 2060,3505 2034,3505 2028,3505
  region net +5V: 2055,1211 2037,1193 2037,1186 2062,1186 2063,1187
  region net +5V: 2052,1360 2087,1360 2087,1160 2052,1160
  region net +5V: 2087,1160 2009,1160 2008,1161 2008,1197 2087,1197
  region net +5V: 2224,1185 2224,1184 2205,1165 2200.06,1169.94 2200.06,1187.24
  region net +5V: 2185,1203 2193,1211 2273,1211 2273,1181 2189.19,1181
  region net +5V: 2185,1139 2210,1139 2210,1203 2185,1203
  region net NetC31_1: 2372,1139.77 2419,1139.77 2419,990 2372,990
  region net NetC32_1: 2278,1139.77 2323,1139.77 2323,990 2278,990
  region net +5V: 3125.4,1559.26 3190.4,1559.26 3190.4,1509.26 3125.4,1509.26
  region net +5V: 2924,1558.63 2989,1558.63 2989,1508.63 2924,1508.63
  region net +5V: 2720,1558.63 2785,1558.63 2785,1508.63 2720,1508.63
  region net +5V: 2516,1558 2581,1558 2581,1508 2516,1508
  region net +5V: 2340,1677 2430,1677 2430,1656 2340,1656
  region net +5V: 2340,1831 2430,1831 2430,1810 2340,1810
  region net +5V: 931.2,1803.2 946.8,1818.8 936.8,1828.8 924.8,1828.8
  region net +5V: 915,1870 915,1869 941,1843 931,1833 923.68,1833 897.69,1858.99
  region net +5V: 874,1842 874,1903 921,1903 921,1902 921,1842
  region net +3V3: 709,2158 682,2131 682,2129 722,2129 730,2137
  region net +3V3: 349,1847 349,1781 485,1781 512,1808 512,2076 530,2094 729,2094 744,2109 744,2271 706,2271 706,2140 479,2140 457,2118 457,2110 457,1862 445,1847
  region net +5V: 1140,2749 1172,2707.5 1198,2707.5 1236.5,2749
  region net +5V: 1259,2746 1302,2703 1363,2703 1407,2747 1409,2756
  region net +5V: 1227,2836 1196,2805 1196,2802 1245,2802 1246,2803
  region net +5V: 684.5,1826.5 724,1787 716,1779 665.86,1779 654.93,1789.93
  region net +5V: 1373,1878 1374,2798 1287,2798 1281,2804
  region net +5V: 1288,2742 1288,1945 1264,1921 1200,1921 1187,1908 1187,1860 1180,1853 882,1853 874,1845 874,1815 860,1801 685.46,1801 685.46,1893 639,1893 639,1782 653,1768 918,1768 933,1783 933,1815 1241,1815 1286,1860 1356,1860 1373,1878
  region net +5V: 1150,2444 1170,2464 1171,2464 1171,2435 1176,2430
  region net +5V: 1168,2403 1168,2762 1167.44,2762.56 1170.89,2766 1201,2766 1201,2401.26
  region net +5V: 1674,2896 1674,2854 1664,2844 1265,2844 1256,2853 1256,2893 1221,2893 1221,2816 1237,2816 765,2816 765,2743 765,2739 767,2739 1762,2739 1787,2764 1787,2896
  region net NetC8_1: 2719.55,3761 2325,3761 2324,3760 2324,3743.46
  region net NetC8_1: 3053,3412 3084.12,3443.12 3206.12,3338.12 3185,3317 3148,3317 3095,3370
  region net NetC8_1: 3556,102 3521,67 3195,67 3180,82 3180,129
  region net +3V3: 619,2075 619,2128 653,2128 653,2123 653,2075
  region net +3V3: 902,2006 902,2002 902,1977 816,1977 816,2006
  region net +3V3: 1088,2198 1088,2170 1184.44,2170 1184.44,2198
  region net +3V3: 1173,2028 1173,2026 1149,2002 1163,1988 1183,1988 1183,2009 1194,2020
  region net +3V3: 1017,1976 1017,2011 1167,2011 1167,2251 1203,2251 1203,1994 1185,1976
  region net +5V: 1146,2424 1147,2424 1179,2392 1183.89,2396.89 1183.89,2422.11 1173.89,2422.11 1160,2436
  region net +5V: 1042,2387 1042,2418 1045,2421 1168,2421 1168,2285 1169,2284 1201,2284 1201,2427 1184,2444 1034,2444 1025,2435 1025,2387
  region net +3V3: 2275,3136 2350,3136 2350,3355 2431,3355 2431,3291 2676,3291 2676,3388 2275,3388
  region net +5V: 1787,2896 1674,2896 1674,3301.84 1720.16,3348 2268,3348 2268,3285.56 1830.14,3285.56 1787,3242.42
  region net NetC14_2: 600,3061 625,3061 635.5,3071.5 635.5,3151 652,3169 659,3169 908,3169 974,3103 974,3060 1077,3060 1075,3150 1006,3150 950,3206 634,3206 615,3187 615,3102.75 610.82,3097 601,3097
  region net NetD4_2: 1237,3305 1472,3305 1501,3279 1501,3120 1381,3120 1381,3195 1357,3215 1237,3215
  region net NetD4_2: 534,3146 534,3263 575.7,3304.7 1045.26,3304.7 1045.26,3215.26 1045,3215 635,3215 607,3187 607,3144
  region net NetD4_2: 534,3146 534,3105 607,3105 607,3146
  region net NetC14_2: 503,3094 510,3087 515,3087 515,3093.46 519.61,3098.07
  region net NetC20_2: 563,3029 505,3029 488.72,3050 488.72,3059.81 497,3061 511.85,3042 562.58,3042 569.17,3035.41
  region net NetC14_2: 423,3116 316,3116 301,3101 301,3090
  region net NetC14_2: 175,3101 175,3039 424,3039 439,3053 439,3089 443.26,3092.73 508.95,3092.73 508.95,3076.05 534,3051 604,3051 604,3097 535,3097 415,3116 319,3101
  region net NetC9_2: 1312,3533 1370,3533 1370,3454 1312,3454
  region net NetC9_2: 1192,3467 1720,3467 1720,3402 1192,3402
  region net NetC9_2: 2720,3415 2816,3319 2848,3319 2848,3412 2850,3414
  region net NetC9_2: 2800,3462.53 2800,3166 2881,3085 3371,3085 3371,3142 3374,3145 3317,3202 2971,3202 2971,3445 2949,3467
  region net NetC9_2: 3441,541 3350,450 3350,443 3444,443 3495,494 3495,544
  region net NetC9_2: 3388.73,479 3428,479 3428,2989 3292,3125 2978,3125 2923,3180 2923,3510 2972,3510 2972,3278 3024,3226 3534,3226 3607,3153 3607,404 3512.56,309.56
  region net NetC8_1: 3207.45,174 3564,174 3649,259 3649,3259 3657,3267 3787,3267 3787,156 3762.5,131.5 3698,67 3229,67 3182,114
  region net NetC8_1: 102,480 3014,480 3014,221 3061,174 3212,174 3212,69 3210,67 836,67 835,68 837,70 837,164 102,164
  region net NetC8_1: 3089,3761 3122,3730.7 3122,3363 3220,3363 3220,3264 3064,3264 3021,3307 3021,3641
  region net NetC8_1: 2564,3679 2564,3673 2568,3669 2991,3669 2994,3669 3016,3645.64 3021,3641 3023,3643 3059,3669 3089,3761 2572,3761
  region net NetC8_1: 2549.45,3725.79 2564,3711.24 2564,3677.24 2608,3677.24 2609,3678.24 2608,3679.24 2608,3724.76
  region net NetC8_1: 2350,3760 2585,3760 2608,3737 2608,3722 2572,3722 2569,3722 2565,3722 2548,3722 2350,3722
  region net NetC8_1: 2290,3628 2301,3628 2305,3632 2305,3741 2324,3760 2350,3760 2350,3722 2336,3708.7 2336,3620 2314,3598 2288.79,3598
  region net NetC9_2: 2694,3645 2974,3645 2974,3267 2956,3270 2956,3447 2694,3447
  region net NetC9_2: 2657,3645 2695,3645 2695,3477 2659,3477 2657,3477
  region net NetC9_2: 2313,3544 2346,3544 2346,3481 2345,3480 2313,3480
  region net NetC9_2: 1919,3501 1943,3477 1943,3473 1917.67,3473 1914.52,3469.86
  region net NetC9_2: 1886,3525 1887,3524 1887,3402 2851,3402 2851,3488 2593,3488 1925,3488 1925,3525
  region net NetIC3_1: 2459,3627 2504,3627 2504,3558 2459,3558
  region net NetIC3_1: 2353,3626 2398,3626 2398,3559 2353,3559
  region net NetC8_1: 2177.28,3628 2290.5,3628 2290.5,3598 2212.72,3598 2212.72,3586.7 2177.28,3586.7
  region net NetC8_2: 2177.28,3673.3 2231,3673.3 2231,3662.81 2290.5,3662.81 2290.5,3639.19 2247.19,3639.19 2233,3639.19 2177.28,3639.19
  region net VCC: 1730,4260 1916,4260 1945,4231 1945,3799 1878,3799 1878,4200 1869,4209 1730,4209
  region net VIN: 1683,3910 1788,3910 1788,3839 1683,3839
  region net VIN: 1631,3629 1631,3555 1684,3555 1684,3629
  region net NetC9_2: 1711,3772 1711,3402 1925.19,3402 1925.19,3772
  region net VCC: 1573.64,3633.64 1608,3668 1572,3668
  region net VCC: 1403,3588.51 1403,3651 1517,3651 1531,3665 1531,3688 1545,3702 1686,3702 1686,3663 1576,3663 1576,3606 1558.51,3588.51
  region net VCC: 701,3352 1018,3352 1020,3352 1020,3466 933,3466 933,3486 701,3486
  region net +5V_B: 476,3466 526,3466 547,3445 547,3353 617,3353 628,3353 628,3520 590,3558 476,3558
  region net +5V_B: 383,3798 376,3798 362,3784 362,3654 300,3654 300,3818 342,3860 383,3860
  region net +5V_B: 1609,3874 1589,3854 1598,3845 1611,3845
  region net +5V_B: 1666,3859 1666,3869 1656,3869 1656,3859
  region net +5V_B: 1666,3860 1666,3830 1634,3798 382,3798 382,3848 382,3860
  region net +5V_B: 1731,4031 1705,4005 1640.75,4005 1606.49,3970.75 1606.49,3851 1649,3851 1666,3868 1666,3957 1735.96,3957 1780.96,4002 1780.96,4031
  region net +5V_B: 1731,4175 1781,4175 1781,4031 1740,4031 1738,4031 1736,4031 1731,4031
  region net VIN: 555,3672 621,3672 621,3642 638,3625 908,3625 908,3591 566,3591 555,3602
  region net +5V_B: 199,3677 276,3677 276,3654 199,3654
  region net +5V_B: 199,3488 276,3488 276,3466 199,3466
  region net +5V_B: 252.93,3677 476,3677 476,3466 252.93,3466
  region net NetC4_1: 1479,4003 1650,4162 1650,4217 1710,4217 1710,4118 1545.28,3958.45
  region net NetC4_1: 1130,4028 1130,3875 1549,3875 1549,4018 1549,4028
  region net NetC3_1: 439,4116 678.43,3876.57 1005,3876.57 1005,4013 977,4013 851,4139 610,4139 578,4171 578,4265 439,4265
  region net NetC3_1: 440,4265 509,4265 510,4264 510,4115 440,4115
Bottom Layer:
  region net +5V: 2379,4263 2848,4263 2848,4151 2379,4151
  region net +5V: 2023,3368 1992.5,3337.5 2005.69,3324.31 2044.31,3324.31
  region net +5V: 2020,3534 2069,3534 2069,3296 2034,3261 1998,3261 1998,3344 1997,3345 2020,3345
  region net +5V: 2038,1164 2213,1164 2213,1133 2037,1133
  region net +5V: 2002,898 2002,1199 2041,1199 2041,899 2042,898
  region net +5V: 1103,1131 1103,894 1145,894 1145,897 1146,903 1146,1133
  region net +5V: 295,1889 240,1834 224,1834 224,1890.52 216.26,1898.26
  region net +5V: 349,1952 188,1952 169,1933 169,1878 377.38,1878
  region net +5V: 254,1932 199,1932 169,1902 169,844 202,811 214,811 2946,811 3009,874 3009,1527.37 3011.56,1529.93 3003.49,1538 2883,1538 2883,927 2864,908 2826,908 307,908 254,961
  region net +5V: 2401,1837 2441,1837 2441,1576 2449,1568 3170,1568 3170,1519 3169.81,1518.81 2422.19,1518.81 2403,1538
  region net +5V: 600,1809 600,1804 638,1766 652,1780 652,1816.93
  region net +5V: 474,1899 474,1886 519,1841 529,1851 529,1884
  region net +5V: 348,1951 349,1952 531,1952 545,1938 545,1895 581,1859 664,1859 670,1853 670,1636 618,1636 618,1802 512,1802 499,1815 499,1878 348,1878
  region net VCC: 1439,3553 1439,3551 1432,3544 1280,3544 1280,3563 1278,3565
  region net VCC: 845.45,3708.55 931,3623 963.45,3623
  region net VCC: 1321,3564 1316,3564 1273,3521 1247,3547 1247,3567 1255,3567 1285,3597
  region net VCC: 1372,3777 1317,3722 1351,3722 1372,3701 1395,3724 1395,3745
  region net +5V: 1103,1273 1146,1273 1146,1130 1103,1130
  region net +3V3: 871,2003 871,2014 901,2014 915,2000 915,1999
  region net +3V3: 871,1987 883,1975 1090.95,1975 1119,2005 1119,2141 1079,2141 1079,2017 1067,2005 871,2005
  region net +3V3: 871,2008 871,2089 860,2100 624,2100 624,2126 889,2126 901,2114 901,2007
  region net +3V3: 1791,2781 1692,2682 1692,2678 1819,2678 1828,2669
  region net +3V3: 2594.96,3381 2683,3381 2683,3157 2659,3133 1875,3133 1863,3121 1863,2692 1821,2650 1416,2650 1381,2615 1381,2164 1355,2138 1079,2138 1079,2222 1249,2222 1291,2264 1290,2265 1290,2679 1346,2735 1780,2735 1780,3156 1836,3212 2573,3212 2597,3236
  region net +5V: 767,2814 768,2813 768,2745 1687,2745 1695,2745 1762,2808 1762,3194 1829,3261 2003,3261 2003,3345 1735,3345 1634,3244 1633,3244 1633,2871 1576,2814 774,2814
  region net VIN: 835,3538 912,3538 912,3368 917,3363 1593,3363 1631,3401 1631,3555 1714,3555 1714,3358 1636,3280 877.57,3280 835,3322.57
  region net NetIC3_1: 2363,3586 2495,3586 2495,3562 2363,3562
  region net VCC: 1861,3910 1860,3906 1886,3880 1897.17,3891.17 1897.17,3905.84
  region net VCC: 1439,3730 1365,3730 1365,3955 1404,3994 1907,3994 1930,3971 1930,3799 1877,3799 1877,3904 1715,3904 1457,3904 1439,3886
  region net VIN: 1631,3555 1714,3555 1714,3891 1631,3891
  region net VCC: 1439,3744 915,3744 478,3744 478,3645 921,3645 921,3395 1289,3395 1289,3552 1439,3552
  region net VIN: 314,3187 174,3187 174,3118 383,3118 442,3187 442,3473 507,3538 912,3538 912,3627 409,3627 340,3558 340,3217

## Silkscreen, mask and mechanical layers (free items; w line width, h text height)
Top Overlay:
  text "12VDC" at 300,4393.14 h70.87
  text "NC" at 2216,4090.14 h70.87
  text "RELAY" at 2096,3979.35 h70.87
  text "TYPE C" at 10,3893.14 h70.87
  text "5V" at 2226,3880.14 h70.87
  text "220VAC" at 3553.21,3416.93 h70.87 r90
  text "5V" at 870.72,2769.66 h59.06
  text "MISO" at 500.72,2759.66 h59.06
  text "SCK" at 510.72,2659.66 h59.06
  text "MOSI" at 870.72,2659.66 h59.06
  text "RESET" at 470.72,2559.66 h59.06
  text "GND" at 870.72,2559.66 h59.06
  text "PB5" at 1783,2358.14 h70.87
  text "SCL" at 203,2350.14 h70.87
  text "5V" at 2750,2293.14 h70.87
  text "NC" at 2950,2293.14 h70.87
  text "D1" at 2850,2292.35 h70.87
  text "PB4" at 1783,2257.35 h70.87
  text "SDA" at 193,2250.14 h70.87
  text "PB3" at 1783,2158.14 h70.87
  text "AREF" at 153,2149.35 h70.87
  text "5V" at 2748,2089.14 h70.87
  text "NC" at 2948,2089.14 h70.87
  text "D2" at 2848,2088.35 h70.87
  text "PB2" at 1783,2057.35 h70.87
  text "GND" at 183,2050.14 h70.87
  text "PB1" at 1783,1957.35 h70.87
  text "5V" at 2750.26,1896.25 h70.87
  text "D3" at 2850.26,1896.25 h70.87
  text "NC" at 2950.26,1896.25 h70.87
  text "5V" at 223.79,1886.31 h70.87
  text "PB0" at 1783,1858.14 h70.87
  text "3V3" at 203.79,1786.31 h70.87
  text "GND" at 183.79,1686.31 h70.87
  text "5V" at 2752.88,1681.76 h70.87
  text "D4" at 2852.88,1680.97 h70.87
  text "NC" at 2952.88,1681.76 h70.87
  text "PD7" at 1779.39,1645.24 h70.87
  text "RESET" at 113.79,1586.31 h70.87
  text "PD6" at 1779.39,1546.03 h70.87
  text "ADC0" at 153,1450.14 h70.87
  text "PC0" at 453,1450.14 h70.87
  text "PD5" at 1779.06,1446.03 h70.87
  text "PC1" at 453,1350.14 h70.87
  text "PD4" at 1779.59,1345.24 h70.87
  text "ADC1" at 153,1340.14 h70.87
  text "PC2" at 453,1250.14 h70.87
  text "PD3" at 1779.39,1246.03 h70.87
  text "ADC2" at 153,1240.14 h70.87
  text "ADC3" at 153,1150.14 h70.87
  text "PC3" at 453,1150.14 h70.87
  text "PD2" at 1779.85,1145.24 h70.87
  text ">" at 1603,1050.4 h70.87
  text "TX" at 1513,1047.35 h70.87
  text "PD1" at 1788.18,1045.24 h70.87
  text "ADC4" at 153,1040.14 h70.87
  text "PC4/SDA" at 443,1040.14 h70.87
  text "PD0" at 1779.52,946.03 h70.87
  text "ADC5" at 153,940.14 h70.87
  text "PC5/SCL" at 443,940.14 h70.87
  text "RX<" at 1513,937.35 h70.87
Bottom Overlay:
  text "GND" at 2239.58,4467.74 h70.87
  text "V_ADAPTER" at 1764.93,4213.95 h70.87
  text "V_TYPEC" at 571.93,3696.6 h70.87
  text "V_BAT" at 1294.93,3485.95 h70.87
  text "5V" at 1943,3284.79 h70.87
  text "3V3" at 2739,3278.79 h70.87
  text "V_IN" at 373.59,3015.42 h70.87 r270
  text "GND" at 3281.79,2877 h70.87 r270
  text "3V3_DEBUG" at 1140,2267.95 h70.87
  text "5V_MCU" at 1085,1133.6 h70.87
  text "GND" at 1525,679.79 h70.87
